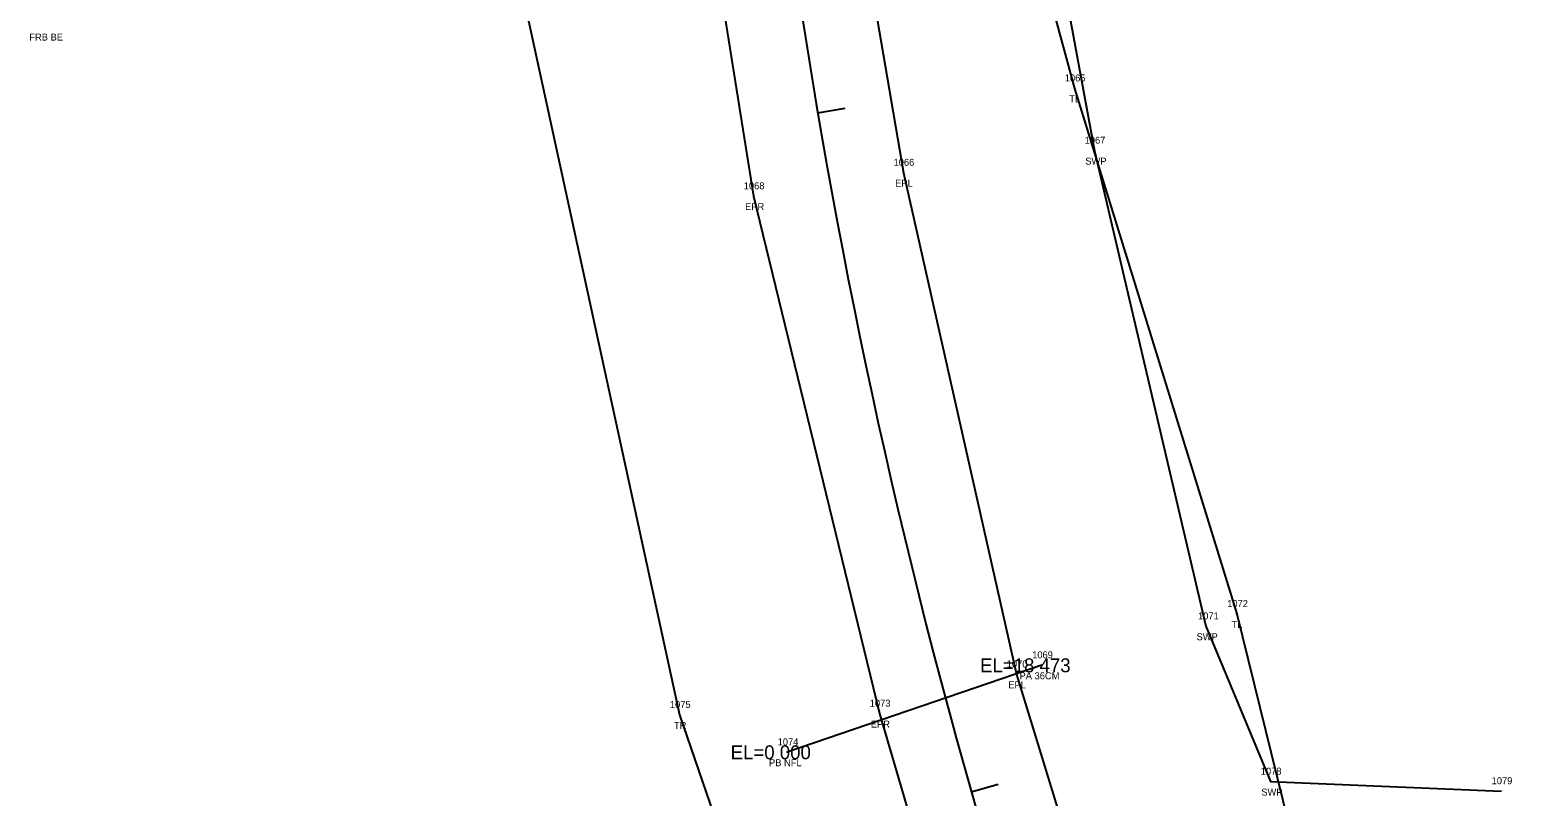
# Model space of a CAD drawing. Extents: x 2432632 to 2433497, y 684847 to 688233.
# Drawn here: x 2432824.8 to 2433041.4, y 686912.6 to 687022.7 of the extents above; entities that cross this region are included whole.
import ezdxf

# ---------------------------------------------------------------- set-up
doc = ezdxf.new("R2010")
doc.units = 0
for name, color, linetype in [('RD_EX_DR_Pipe', 7, 'Continuous'), ('RD_EX_DR_Pipe_txCode', 7, 'Continuous'), ('RD_EX_Fence_Other_txCode', 7, 'Continuous'), ('RD_EX_H2O', 7, 'Continuous'), ('RD_EX_H2O_txCode', 7, 'Continuous'), ('RD_EX_Road', 7, 'Continuous'), ('RD_EX_Road_txCode', 7, 'Continuous'), ('RD_EX_VEG', 7, 'Continuous'), ('RD_EX_VEG_txCode', 7, 'Continuous'), ('RD_HC_Cl', 7, 'Continuous'), ('RD_HC_Data_Tic', 7, 'Continuous'), ('RD_SMD_Locator', 7, 'Continuous'), ('RD_TX_Pipe_ElevEX', 7, 'Continuous')]:
    doc.layers.add(name, color=color, linetype=linetype)

msp = doc.modelspace()

# ---------------------------------------------------------------- linework, layer by layer
at = {"layer": 'RD_EX_DR_Pipe'}
msp.add_line((2432970.13, 686931.53), (2432933.54, 686919.04), dxfattribs=at)
at = {"layer": 'RD_EX_H2O'}
msp.add_lwpolyline([(2432997.82, 687055.15), (2432973.49, 687028.01), (2432977.67, 687005.43), (2432993.65, 686937.13), (2433002.95, 686914.83), (2433036.11, 686913.46)], dxfattribs=at)
at = {"layer": 'RD_EX_Road'}
for points in [[(2433130.63, 688090.22), (2433103.18, 687988.73), (2433075.68, 687887.89), (2433049.83, 687790.75), (2433022.33, 687689.17), (2432994.76, 687586.82), (2432966.23, 687480.17), (2432943.15, 687390.42), (2432931.4, 687334.3), (2432921.83, 687273.88), (2432915.64, 687215.4), (2432913.86, 687159.12), (2432915.08, 687107.55), (2432919.97, 687053.4), (2432928.7, 686998.89), (2432946.77, 686924.59), (2432964.57, 686864), (2432997.3, 686766.34), (2433031.44, 686666.38), (2433066.06, 686565.78), (2433098.73, 686469.74)], [(2432986.34, 687474.01), (2432964, 687384.38), (2432952.4, 687330.76), (2432943.09, 687273.42), (2432937.12, 687213.43), (2432935.51, 687158.7), (2432936.54, 687110.38), (2432944.97, 687033.04), (2432950.24, 687002.26), (2432966.49, 686930.23), (2432984.9, 686870.1)]]:
    msp.add_lwpolyline(points, dxfattribs=at)
at = {"layer": 'RD_EX_VEG'}
for points in [[(2433112.43, 688094.61), (2433041.17, 687898.89), (2432988.9, 687699.78), (2432947.96, 687578.08), (2432935.9, 687556.87), (2432944.3, 687538.7), (2432913.88, 687397.98), (2432902.4, 687330.02), (2432885.78, 687157.56), (2432894.43, 687032.93), (2432918.07, 686924.4), (2432974.73, 686759.54), (2433073.82, 686456.42), (2433099.9, 686365.23), (2433115.47, 686257.21), (2433114.64, 686158.77), (2433095.68, 686092.78)], [(2433166.25, 688082.87), (2433111.93, 687876.69), (2433067.75, 687703.46), (2433065.05, 687678.03), (2433052.74, 687645.62), (2433005.45, 687469.88), (2432979.96, 687326.61), (2432966.8, 687267.34), (2432959.05, 687210.65), (2432959.25, 687071.62), (2432974.82, 687014.37), (2432998.13, 686938.9), (2433012.99, 686878.7), (2433054.45, 686782.35), (2433123.54, 686586.06), (2433129.82, 686546.35), (2433158.34, 686434.26), (2433192.79, 686274.67), (2433189.42, 686162.6), (2433197.4, 686074.41)]]:
    msp.add_lwpolyline(points, dxfattribs=at)
at = {"layer": 'RD_HC_Cl'}
msp.add_arc((2433840.56, 687163.67), 915.47, 164.98581, 198.81644, dxfattribs=at)
at = {"layer": 'RD_HC_Data_Tic'}
for p, q in [((2432937.93, 687010.85), (2432941.88, 687011.52)), ((2432959.97, 686913.36), (2432963.82, 686914.46))]:
    msp.add_line(p, q, dxfattribs=at)
at = {"layer": 'RD_SMD_Locator'}
for centre in [(2432974.82, 687014.37), (2432977.67, 687005.43), (2432950.24, 687002.26), (2432928.7, 686998.89), (2432998.13, 686938.9), (2432993.65, 686937.13), (2432970.13, 686931.53), (2432966.49, 686930.23), (2432946.77, 686924.59), (2432918.07, 686924.4), (2432933.54, 686919.04), (2433002.95, 686914.83), (2433036.11, 686913.46)]:
    msp.add_circle(centre, 0.001, dxfattribs=at)

# ---------------------------------------------------------------- texts
at = {"layer": 'RD_EX_DR_Pipe_txCode'}
for s, p in [('1069', (2432968.72, 686932.53)), ('PA 36CM', (2432966.91, 686929.53)), ('1074', (2432932.16, 686920.04)), ('PB NFL', (2432930.92, 686917.04))]:
    msp.add_text(s, height=1, dxfattribs=at).set_placement(p)
at = {"layer": 'RD_EX_Fence_Other_txCode'}
msp.add_text('FRB BE', height=1, dxfattribs=at).set_placement((2432824.66, 687021.24))
at = {"layer": 'RD_EX_H2O_txCode'}
for s, p in [('1067', (2432976.26, 687006.43)), ('SWP', (2432976.35, 687003.43)), ('1071', (2432992.55, 686938.13)), ('SWP', (2432992.34, 686935.13)), ('1078', (2433001.56, 686915.83)), ('SWP', (2433001.64, 686912.83)), ('1079', (2433034.73, 686914.46))]:
    msp.add_text(s, height=1, dxfattribs=at).set_placement(p)
at = {"layer": 'RD_EX_Road_txCode'}
for s, p in [('1066', (2432948.81, 687003.26)), ('1068', (2432927.29, 686999.89)), ('EPL', (2432949.04, 687000.26)), ('EPR', (2432927.48, 686996.89)), ('1070', (2432965.07, 686931.23)), ('EPL', (2432965.29, 686928.23)), ('1073', (2432945.39, 686925.59)), ('EPR', (2432945.54, 686922.59))]:
    msp.add_text(s, height=1, dxfattribs=at).set_placement(p)
at = {"layer": 'RD_EX_VEG_txCode'}
for s, p in [('1065', (2432973.41, 687015.37)), ('TL', (2432974.05, 687012.37)), ('1072', (2432996.74, 686939.9)), ('TL', (2432997.36, 686936.9)), ('1075', (2432916.68, 686925.4)), ('TR', (2432917.27, 686922.4))]:
    msp.add_text(s, height=1, dxfattribs=at).set_placement(p)
at = {"layer": 'RD_TX_Pipe_ElevEX'}
for s, p in [('EL=18 473  ', (2432961.23, 686930.53)), ('EL=0 000 ', (2432925.4, 686918.04))]:
    msp.add_text(s, height=2, dxfattribs=at).set_placement(p)

doc.saveas('drawing.dxf')
